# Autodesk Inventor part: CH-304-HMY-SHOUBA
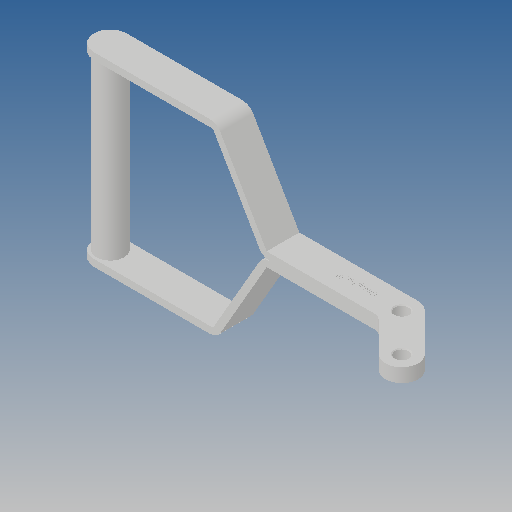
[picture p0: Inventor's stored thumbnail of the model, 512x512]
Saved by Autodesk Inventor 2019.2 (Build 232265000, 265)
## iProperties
Created: 2015-08
Part Number: CH-304-HMY-SHOUBA
Material: Ogólny
Document SubType Name: Modeling
Designer: CADENGINEERING4
Density: 1 g/cm^3
Appearance: Domyślna
Author: CADENGINEERING4
Revision Number: ÈÎºÎ
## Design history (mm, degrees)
feature "ÇÐ³ý-À­Éì2"
node "Bryła1"
